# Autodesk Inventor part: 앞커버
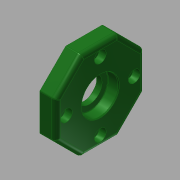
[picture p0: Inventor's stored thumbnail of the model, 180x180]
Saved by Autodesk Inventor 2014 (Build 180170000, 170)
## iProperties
Created: 2015-11
Part Number: 앞커버
Material: 알루미늄 6061
Document SubType Name: Modeling
Designer: mduedu
Density: 1 g/cm^3
Appearance: Smooth - Dark Forest Green
Author: mduedu
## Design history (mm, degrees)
sketch "스케치5" dims "d66" = 60
  geometry: L1 (12.426, 30)-(30, 12.426); L2 (30, 12.426)-(30, -12.426); L3 (30, -12.426)-(12.426, -30); L4 (12.426, -30)-(-12.426, -30); L5 (-12.426, -30)-(-30, -12.426); L6 (-30, -12.426)-(-30, 12.426); L7 (-30, 12.426)-(-12.426, 30); L8 (-12.426, 30)-(12.426, 30); 4 further points
  constraints: 16 end point, 2 coincident, 2 vertical alignment, 1 midpoint, 19 other
extrude "돌출2" new body sketch "스케치5" distance "d67" = 11; taper "d68" = 0 deg
sketch "스케치6"
  geometry: C1 r 16 at (0, 0); 1 further point
  constraints: 1 centre point, 1 coincident
  dimensions: "d69" = 32 diameter of C1
extrude "돌출3" join sketch "스케치6" distance "d70" = 3; taper "d71" = 0 deg
hole "구멍7" diameter "d98" = 25; stored, may be unused: countersink angle "d102" = 90 deg, drill point angle "d104" = 0 deg; dims "d96" = 10, "d97" = 10, "d99" = 6, "d100" = 4, "d101" = 2, "d103" = 3
hole "구멍8" diameter "d107" = 25; stored, may be unused: countersink angle "d111" = 90 deg, drill point angle "d113" = 0 deg; dims "d108" = 6, "d109" = 4, "d110" = 2, "d112" = 7.3, "d143" = 10, "d144" = 10
hole "구멍9" diameter "d116" = 17; stored, may be unused: countersink angle "d120" = 90 deg, drill point angle "d122" = 0 deg; dims "d114" = 10, "d115" = 10, "d117" = 6, "d118" = 4, "d119" = 2, "d121" = 7.7
chamfer "모따기2" distance "d123" = 0.7; stored, may be unused: second distance "d124" = 2, angle "d125" = 30 deg
fillet "모깎기11" dims "d126" = 0.3
fillet "모깎기12" dims "d127" = 1
fillet "모깎기13" dims "d128" = 3
fillet "모깎기14" dims "d129" = 3
fillet "모깎기15" dims "d130" = 0.3
sketch "스케치8" dims "d131" = 46
  geometry: 3 further points
  constraints: 2 vertical alignment, 1 coincident, 2 other
hole "구멍10" sketch "스케치8" at (0, 23) diameter "d132" = 4.5; stored, may be unused: countersink angle "d136" = 90 deg, drill point angle "d138" = 0 deg; dims "d133" = 6, "d134" = 8, "d135" = 4.6, "d137" = 7.7
node "솔리드2"
pattern_circular "원형 패턴4" dims angle "d140" = 360 deg
